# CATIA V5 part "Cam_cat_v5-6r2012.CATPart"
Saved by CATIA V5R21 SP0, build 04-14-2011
Part number: Cam
Bounding box of the stored display mesh (mm): x -10 to 60, y -35 to 35, z -50 to 30
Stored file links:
  D:\CATIA V5R21 E-RESOURCES\CATIA-V5R21\catia-v5r21-Tut\c16-catia-v5r21-tut\c16-catia-v5r21-tut03\Cam_cat_v5r21.CATPart
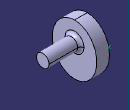
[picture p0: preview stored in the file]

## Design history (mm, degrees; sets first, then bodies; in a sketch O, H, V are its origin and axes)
Body1 (main body)
  Sketch1 on yz-plane, origin (0, 0, 0), H (0, 1, 0), V (0, 0, 1)
    point P1 (0, -10)
    ellipse A1 centre (0, -10) semi-axes 40, 35 rotation 90
    point P2 (0, 30)
    "Radius" A1 = 40
    distance V A1 = 35
    distance P1 H = 10
    coincidence: P1 V, P2 V, A1 P2
  Pad1: profile Sketch1, direction (1, 0, 0), length 10, mirrored extent
  Sketch2 on end face of Pad1, origin (10, 0, 0), H (0, 1, 0), V (0, 0, 1)
    circle A1 centre (0, 0) radius 10
    radius A1 = 10
  Pad2: profile Sketch2, direction (1, 0, 0), length 50
  Sketch3 on start face of Pad1, origin (-10, 0, 0), H (0, -1, 0), V (0, 0, 1)
    point P1 (-33.8886, 0)
    reference projected curve E1 from edge [start face of Pad1 | face of Pad1 from Sketch1.A1]
    coincidence: P1 H, P1 E1
  Fillet1: radius 5, on edge [end face of Pad1 | face of Pad2 from Sketch2.A1]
